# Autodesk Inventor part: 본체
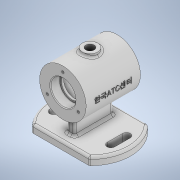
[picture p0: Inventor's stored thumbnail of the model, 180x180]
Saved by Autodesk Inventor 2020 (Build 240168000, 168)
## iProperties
Created: 2021-09
Part Number: 본체
Material: Generic
Document SubType Name: Modeling
Designer: Administrator
Density: 1 g/cm^3
Appearance: Default
Author: Administrator
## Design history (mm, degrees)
sketch "스케치1"
  geometry: C1 r 30 at (0, 0); 1 further point
  constraints: 1 centre point, 1 coincident
  dimensions: "d0" = 60 diameter of C1
extrude "돌출1" new body sketch "스케치1" stored distance "d1" = 70; taper "d2" = 0 deg
node "작업 평면1"
sketch "스케치2"
  geometry: C1 r 52.5 at (0, 0); 1 further point
  constraints: 1 centre point, 1 coincident
  dimensions: "d4" = 105 diameter of C1
extrude "돌출2" join sketch "스케치2" distance "d5" = 10; taper "d6" = 0 deg
sketch "스케치3"
  geometry: L1 (36.458, 37.5)-(-36.458, 37.5); L2 (-36.458, -37.5)-(36.458, -37.5); L3 (-36.458, -37.5)-(-36.742, -37.5); L4 (36.458, -37.5)-(36.742, -37.5); L5 (36.458, 37.5)-(36.742, 37.5); L6 (-36.458, 37.5)-(-36.742, 37.5); A1 r 52.5 centre (0, 0) between (-36.742, -37.5) and (36.742, -37.5) reference; A2 r 52.5 centre (0, 0) between (-36.742, -37.5) and (36.742, -37.5) reference; 3 further points
  constraints: 12 end point, 4 horizontal, 4 point on circle, 1 parallel, 1 point on line
  dimensions: "d7" = 75 distance of L1.end L2.start
extrude "돌출3" cut sketch "스케치3" distance "d8" = 10; taper "d9" = 0 deg
sketch "스케치4"
  geometry: L1 (-25.13, 25)-(-60.104, 25); L2 (-60.104, 25)-(-60.104, -25); L3 (-60.104, -25)-(-25.13, -25); L4 (-25.13, -25)-(-25.13, 25); 2 further points
  constraints: 8 end point, 2 parallel, 1 horizontal, 1 horizontal alignment, 1 midpoint, 1 perpendicular
  dimensions: "d10" = 50 distance of L1.end L2.end
extrude "돌출4" join sketch "스케치4" stored distance "d11" = 10; taper "d12" = 0 deg
sketch "스케치5"
  geometry: L1 (-37, -10)-(-37, 10); L2 (-32, -10)-(-32, 10); L3 (-42, 10)-(-42, -10); L4 (0, 0)-(0, 55.124); L5 (37, -10)-(37, 10); L6 (32, -10)-(32, 10); L7 (42, 10)-(42, -10); A1 r 5 centre (-37, -10) between (-42, -10) and (-32, -10); A2 r 5 centre (-37, 10) between (-32, 10) and (-42, 10); A3 r 5 centre (37, -10) between (32, -10) and (42, -10); A4 r 5 centre (37, 10) between (42, 10) and (32, 10); 2 further points
  constraints: 18 end point, 8 point on circle, 7 symmetric about line, 4 centre point, 4 tangent, 2 vertical, 1 horizontal alignment, 1 midpoint, 1 parallel, 2 other
  dimensions: "d13" = 20 distance of L1.start L1.end; "d14" = 10 diameter of A2; "d15" = 37 distance of point (-37, 0) L4.start
extrude "돌출5" cut sketch "스케치5" distance "d16" = 10; taper "d17" = 0 deg
sketch "스케치6"
  geometry: L1 (30, 35)-(-30, 35) reference; L2 (0, 35)-(16, 35); L3 (16, 35)-(16, 23.3); L4 (15.7, 23)-(0, 23); L5 (0, 23)-(0, 35); L6 (0, 23)-(14, 23); L7 (14, 23)-(14, 20); L8 (14, 20)-(0, 20); L9 (0, 20)-(0, 23); L10 (0, 20)-(25, 20); L11 (25, 20)-(25, -20); L12 (25, -20)-(0, -20); L13 (0, -20)-(0, 20); L14 (0, -20)-(14, -20); L15 (14, -20)-(14, -23); L16 (14, -23)-(0, -23); L17 (0, -23)-(0, -20); L18 (-30, -35)-(30, -35) reference; L19 (0, -23)-(15.7, -23); L20 (16, -23.3)-(16, -35); L21 (16, -35)-(0, -35); L22 (0, -35)-(0, -23); A1 r 0.3 centre (15.7, 23.3) between (15.7, 23) and (16, 23.3); A2 r 0.3 centre (15.7, -23.3) between (16, -23.3) and (15.7, -23); 11 further points
  constraints: 40 end point, 10 parallel, 5 horizontal, 5 perpendicular, 5 point on line, 4 point on circle, 4 tangent, 3 midpoint, 2 centre point, 1 equal radius, 1 horizontal alignment
  dimensions: "d18" = 50 diameter of L11 L13; "d19" = 40 distance of L10.end L11.end; "d20" = 32 diameter of L3 L5; "d21" = 28 diameter of L7 L9; "d22" = 32 diameter of L20 L22; "d23" = 28 diameter of L15 L17; "d24" = 12 distance of point (16, -23) L20.end; "d25" = 12 distance of L2.end point (16, 23); "d26" = 0.3 radius of A1
revolve "회전1" sketch "스케치6" stored, may be unused: angle "d27" = 90 deg
node "작업 평면2"
sketch "스케치7"
  geometry: C1 r 10 at (0, 0); 1 further point
  constraints: 1 centre point, 1 coincident
  dimensions: "d29" = 20 diameter of C1
extrude "돌출6" join sketch "스케치7" stored distance "d30" = 10; taper "d31" = 0 deg
sketch "스케치8"
  geometry: C1 r 10 at (0, 0) reference; 2 further points
  constraints: 1 coincident
hole "구멍1" sketch "스케치8" at (0, 0) diameter "d32" = 10.917; stored, may be unused: countersink angle "d36" = 90 deg, drill point angle "d38" = 118 deg; dims "d33" = 24, "d34" = 4, "d35" = 2, "d37" = 29.1
sketch "스케치9" dims "d39" = 46
  geometry: C1 r 16 at (0, 0) reference; 3 further points
  constraints: 2 vertical alignment, 1 coincident, 2 other
hole "구멍2" sketch "스케치9" at (0, 23) diameter "d40" = 3.242; stored, may be unused: countersink angle "d44" = 90 deg, drill point angle "d46" = 118 deg; dims "d41" = 8, "d42" = 4, "d43" = 2, "d45" = 10
node "작업 평면3"
sketch "스케치10"
  geometry: L1 (30, 35)-(-30, 35) reference; L2 (30, -35)-(30, 35) reference; 2 further points
  constraints: 1 coincident, 1 other
  dimensions: "d63" = 35 distance from line of point (0, 0) L1; "d64" = 30 distance from line of point (0, 0) L2
feature "엠보싱1" sketch "스케치10" dims "d52" = 0.5, "d53" = 0
fillet "모깎기1" dims "d54" = 3
fillet "모깎기2" dims "d55" = 3
fillet "모깎기3" dims "d56" = 3
chamfer "모따기1" distance "d57" = 1; stored, may be unused: second distance "d58" = 2, angle "d59" = 45 deg
fillet "모깎기4" dims "d60" = 3
fillet "모깎기5" dims "d61" = 3
fillet "모깎기6" dims "d62" = 3
node "솔리드1"
pattern_circular "원형 패턴1" dims angle "d48" = 360 deg
mirror "미러1"
node "투영된 루프1"
feature "A9D066F2-1C7D-4E18-AEED-F7BC21143FA4" dims "d40" = 3.242, "d41" = 8, "d42" = 4, "d43" = 2, "d44" = 90 deg, "d45" = 10, "d46" = 118 deg
other parameters: "d3" = -62, "d28" = 33
